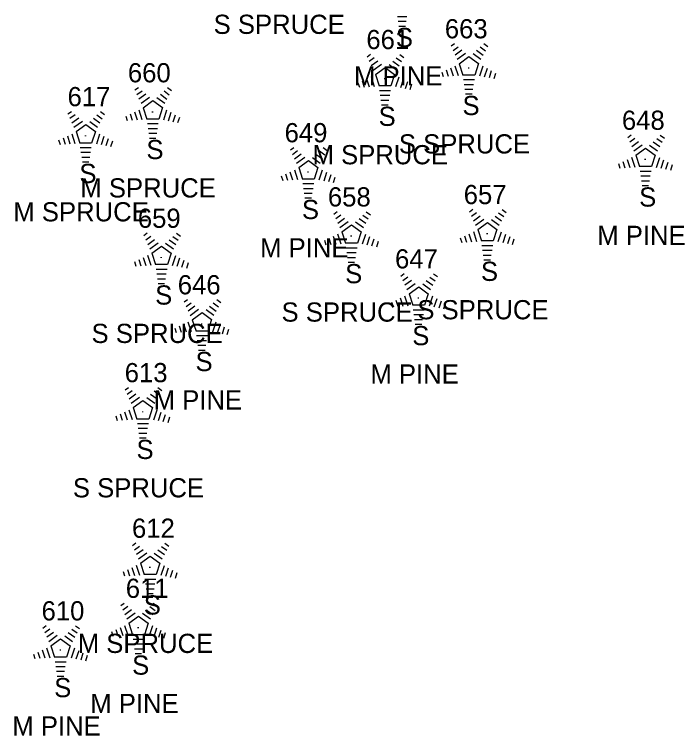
# Model space of a CAD drawing. Extents: x 1545627 to 1546562, y 571176 to 576667.
# Drawn here: x 1546282.1 to 1546351.9, y 572031.2 to 572106.4 of the extents above; entities that cross this region are included whole.
import ezdxf

# ---------------------------------------------------------------- set-up
doc = ezdxf.new("R2010")
doc.units = 0
for name, color, linetype in [('L_A', 7, 'Continuous'), ('L_C', 7, 'Continuous'), ('L_I', 7, 'Continuous'), ('LTC', 7, 'Continuous')]:
    doc.layers.add(name, color=color, linetype=linetype)

msp = doc.modelspace()

# ---------------------------------------------------------------- linework, layer by layer
at = {"layer": 'LTC'}
for p, q in [((1546323.001, 572106.113), (1546322.013, 572106.113)), ((1546322.917, 572105.613), (1546322.086, 572105.613)), ((1546322.834, 572105.113), (1546322.159, 572105.113)), ((1546327.598, 572103.074), (1546327.953, 572103.331)), ((1546327.808, 572102.608), (1546328.337, 572102.992)), ((1546330.996, 572103.314), (1546331.416, 572103.009)), ((1546328.017, 572102.142), (1546328.721, 572102.654)), ((1546328.227, 572101.677), (1546329.105, 572102.314)), ((1546329.883, 572102.269), (1546330.693, 572101.68)), ((1546330.254, 572102.617), (1546330.934, 572102.124)), ((1546330.625, 572102.966), (1546331.175, 572102.567)), ((1546318.855, 572101.947), (1546319.209, 572102.204)), ((1546319.064, 572101.481), (1546319.594, 572101.865)), ((1546319.274, 572101.015), (1546319.978, 572101.527)), ((1546321.511, 572101.49), (1546322.19, 572100.997)), ((1546321.882, 572101.839), (1546322.431, 572101.439)), ((1546322.253, 572102.187), (1546322.672, 572101.882)), ((1546328.451, 572101.222), (1546329.463, 572101.956)), ((1546329.463, 572101.956), (1546330.46, 572101.231)), ((1546319.484, 572100.549), (1546320.362, 572101.187)), ((1546319.708, 572100.094), (1546320.72, 572100.829)), ((1546320.72, 572100.829), (1546321.717, 572100.104)), ((1546321.14, 572101.142), (1546321.949, 572100.553)), ((1546327.541, 572100.786), (1546327.813, 572099.951)), ((1546327.997, 572101.002), (1546328.328, 572099.983)), ((1546328.451, 572101.222), (1546328.839, 572100.028)), ((1546330.46, 572101.231), (1546330.069, 572100.028)), ((1546330.898, 572100.96), (1546330.56, 572099.921)), ((1546319.708, 572100.094), (1546320.095, 572098.901)), ((1546321.717, 572100.104), (1546321.326, 572098.901)), ((1546326.631, 572100.353), (1546326.783, 572099.885)), ((1546327.086, 572100.569), (1546327.298, 572099.918)), ((1546330.069, 572100.028), (1546328.839, 572100.028)), ((1546331.342, 572100.71), (1546331.055, 572099.825)), ((1546331.787, 572100.46), (1546331.55, 572099.73)), ((1546332.231, 572100.209), (1546332.044, 572099.635)), ((1546317.887, 572099.226), (1546318.039, 572098.758)), ((1546318.343, 572099.442), (1546318.554, 572098.791)), ((1546318.798, 572099.659), (1546319.069, 572098.824)), ((1546319.254, 572099.875), (1546319.584, 572098.856)), ((1546322.154, 572099.833), (1546321.816, 572098.794)), ((1546322.599, 572099.583), (1546322.311, 572098.698)), ((1546323.044, 572099.333), (1546322.806, 572098.603)), ((1546330.031, 572099.528), (1546328.886, 572099.528)), ((1546294.657, 572098.487), (1546295.012, 572098.744)), ((1546298.055, 572098.727), (1546298.474, 572098.423)), ((1546321.326, 572098.901), (1546320.095, 572098.901)), ((1546323.488, 572099.082), (1546323.301, 572098.508)), ((1546329.947, 572099.028), (1546328.959, 572099.028)), ((1546329.863, 572098.528), (1546329.031, 572098.528)), ((1546294.867, 572098.021), (1546295.396, 572098.406)), ((1546295.076, 572097.556), (1546295.78, 572098.067)), ((1546295.286, 572097.09), (1546296.164, 572097.728)), ((1546297.313, 572098.031), (1546297.992, 572097.537)), ((1546297.684, 572098.379), (1546298.234, 572097.98)), ((1546321.287, 572098.401), (1546320.143, 572098.401)), ((1546321.204, 572097.901), (1546320.215, 572097.901)), ((1546329.779, 572098.028), (1546329.104, 572098.028)), ((1546295.51, 572096.635), (1546296.522, 572097.369)), ((1546296.522, 572097.369), (1546297.519, 572096.644)), ((1546296.942, 572097.682), (1546297.752, 572097.094)), ((1546321.12, 572097.401), (1546320.288, 572097.401)), ((1546287.671, 572095.998), (1546288.026, 572096.255)), ((1546291.07, 572096.238), (1546291.489, 572095.933)), ((1546295.056, 572096.416), (1546295.387, 572095.396)), ((1546295.51, 572096.635), (1546295.897, 572095.441)), ((1546297.519, 572096.644), (1546297.128, 572095.441)), ((1546297.957, 572096.374), (1546297.619, 572095.334)), ((1546321.036, 572096.901), (1546320.361, 572096.901)), ((1546287.881, 572095.532), (1546288.41, 572095.916)), ((1546288.091, 572095.066), (1546288.794, 572095.578)), ((1546290.328, 572095.541), (1546291.007, 572095.048)), ((1546290.699, 572095.89), (1546291.248, 572095.491)), ((1546293.689, 572095.766), (1546293.842, 572095.298)), ((1546294.145, 572095.983), (1546294.357, 572095.331)), ((1546294.6, 572096.199), (1546294.872, 572095.364)), ((1546298.401, 572096.123), (1546298.114, 572095.239)), ((1546298.846, 572095.873), (1546298.609, 572095.144)), ((1546299.29, 572095.623), (1546299.103, 572095.049)), ((1546288.3, 572094.601), (1546289.179, 572095.238)), ((1546288.525, 572094.146), (1546289.536, 572094.88)), ((1546289.536, 572094.88), (1546290.534, 572094.155)), ((1546289.956, 572095.193), (1546290.766, 572094.604)), ((1546297.128, 572095.441), (1546295.897, 572095.441)), ((1546297.089, 572094.941), (1546295.945, 572094.941)), ((1546288.525, 572094.146), (1546288.912, 572092.952)), ((1546290.534, 572094.155), (1546290.142, 572092.952)), ((1546297.006, 572094.441), (1546296.017, 572094.441)), ((1546286.704, 572093.277), (1546286.856, 572092.809)), ((1546287.159, 572093.493), (1546287.371, 572092.842)), ((1546287.615, 572093.71), (1546287.886, 572092.875)), ((1546288.07, 572093.926), (1546288.401, 572092.907)), ((1546290.971, 572093.884), (1546290.633, 572092.845)), ((1546291.416, 572093.634), (1546291.128, 572092.749)), ((1546291.86, 572093.384), (1546291.623, 572092.654)), ((1546296.922, 572093.941), (1546296.09, 572093.941)), ((1546296.838, 572093.441), (1546296.163, 572093.441)), ((1546346.004, 572093.538), (1546346.358, 572093.795)), ((1546346.213, 572093.072), (1546346.743, 572093.457)), ((1546349.031, 572093.43), (1546349.581, 572093.031)), ((1546349.402, 572093.778), (1546349.821, 572093.474)), ((1546290.142, 572092.952), (1546288.912, 572092.952)), ((1546290.104, 572092.452), (1546288.959, 572092.452)), ((1546292.304, 572093.133), (1546292.118, 572092.559)), ((1546310.865, 572092.241), (1546311.219, 572092.498)), ((1546314.263, 572092.481), (1546314.682, 572092.176)), ((1546346.423, 572092.607), (1546347.127, 572093.118)), ((1546346.633, 572092.141), (1546347.511, 572092.779)), ((1546348.289, 572092.733), (1546349.098, 572092.145)), ((1546348.66, 572093.082), (1546349.339, 572092.588)), ((1546290.02, 572091.952), (1546289.032, 572091.952)), ((1546311.074, 572091.775), (1546311.604, 572092.159)), ((1546311.284, 572091.309), (1546311.988, 572091.821)), ((1546313.521, 572091.784), (1546314.2, 572091.291)), ((1546313.892, 572092.133), (1546314.442, 572091.734)), ((1546346.857, 572091.686), (1546347.869, 572092.42)), ((1546347.869, 572092.42), (1546348.866, 572091.695)), ((1546348.866, 572091.695), (1546348.475, 572090.492)), ((1546289.936, 572091.452), (1546289.105, 572091.452)), ((1546289.853, 572090.952), (1546289.178, 572090.952)), ((1546311.494, 572090.844), (1546312.372, 572091.481)), ((1546311.718, 572090.389), (1546312.73, 572091.123)), ((1546312.73, 572091.123), (1546313.727, 572090.398)), ((1546313.15, 572091.436), (1546313.959, 572090.847)), ((1546345.492, 572091.034), (1546345.703, 572090.382)), ((1546345.947, 572091.25), (1546346.218, 572090.415)), ((1546346.403, 572091.467), (1546346.733, 572090.447)), ((1546346.857, 572091.686), (1546347.244, 572090.492)), ((1546349.303, 572091.425), (1546348.966, 572090.385)), ((1546349.748, 572091.174), (1546349.461, 572090.29)), ((1546311.718, 572090.389), (1546312.105, 572089.195)), ((1546313.727, 572090.398), (1546313.336, 572089.195)), ((1546345.036, 572090.817), (1546345.188, 572090.349)), ((1546348.475, 572090.492), (1546347.244, 572090.492)), ((1546350.193, 572090.924), (1546349.956, 572090.195)), ((1546350.637, 572090.674), (1546350.45, 572090.1)), ((1546309.897, 572089.52), (1546310.049, 572089.052)), ((1546310.353, 572089.736), (1546310.564, 572089.085)), ((1546310.808, 572089.953), (1546311.079, 572089.118)), ((1546311.264, 572090.169), (1546311.594, 572089.15)), ((1546314.164, 572090.127), (1546313.827, 572089.088)), ((1546314.609, 572089.877), (1546314.322, 572088.992)), ((1546315.054, 572089.627), (1546314.817, 572088.897)), ((1546348.436, 572089.992), (1546347.292, 572089.992)), ((1546348.353, 572089.492), (1546347.364, 572089.492)), ((1546313.336, 572089.195), (1546312.105, 572089.195)), ((1546313.297, 572088.695), (1546312.153, 572088.695)), ((1546315.498, 572089.376), (1546315.311, 572088.802)), ((1546348.269, 572088.992), (1546347.437, 572088.992)), ((1546313.214, 572088.195), (1546312.225, 572088.195)), ((1546348.185, 572088.492), (1546347.51, 572088.492)), ((1546313.13, 572087.695), (1546312.298, 572087.695)), ((1546313.046, 572087.195), (1546312.371, 572087.195)), ((1546315.368, 572085.551), (1546315.723, 572085.808)), ((1546318.766, 572085.791), (1546319.186, 572085.487)), ((1546329.521, 572085.795), (1546329.876, 572086.052)), ((1546329.731, 572085.329), (1546330.26, 572085.713)), ((1546332.548, 572085.687), (1546333.098, 572085.288)), ((1546332.919, 572086.035), (1546333.339, 572085.73)), ((1546315.578, 572085.085), (1546316.107, 572085.469)), ((1546315.787, 572084.619), (1546316.491, 572085.131)), ((1546318.024, 572085.094), (1546318.703, 572084.601)), ((1546318.395, 572085.443), (1546318.945, 572085.044)), ((1546329.94, 572084.863), (1546330.644, 572085.375)), ((1546330.15, 572084.398), (1546331.028, 572085.035)), ((1546331.806, 572084.99), (1546332.616, 572084.401)), ((1546332.177, 572085.338), (1546332.856, 572084.845)), ((1546315.997, 572084.154), (1546316.875, 572084.792)), ((1546316.221, 572083.699), (1546317.233, 572084.433)), ((1546317.233, 572084.433), (1546318.23, 572083.708)), ((1546317.653, 572084.746), (1546318.463, 572084.157)), ((1546330.374, 572083.943), (1546331.386, 572084.677)), ((1546331.386, 572084.677), (1546332.383, 572083.952)), ((1546295.569, 572083.326), (1546295.923, 572083.583)), ((1546298.967, 572083.566), (1546299.386, 572083.262)), ((1546315.767, 572083.479), (1546316.098, 572082.46)), ((1546316.221, 572083.699), (1546316.608, 572082.505)), ((1546318.23, 572083.708), (1546317.839, 572082.505)), ((1546318.668, 572083.437), (1546318.33, 572082.398)), ((1546329.464, 572083.507), (1546329.736, 572082.672)), ((1546329.92, 572083.723), (1546330.251, 572082.704)), ((1546330.374, 572083.943), (1546330.761, 572082.749)), ((1546332.383, 572083.952), (1546331.992, 572082.749)), ((1546332.821, 572083.681), (1546332.483, 572082.642)), ((1546333.265, 572083.431), (1546332.978, 572082.546)), ((1546295.778, 572082.86), (1546296.307, 572083.245)), ((1546295.988, 572082.395), (1546296.692, 572082.906)), ((1546298.225, 572082.87), (1546298.904, 572082.376)), ((1546298.596, 572083.218), (1546299.145, 572082.819)), ((1546314.401, 572082.83), (1546314.553, 572082.362)), ((1546314.856, 572083.047), (1546315.068, 572082.395)), ((1546315.311, 572083.263), (1546315.583, 572082.428)), ((1546319.112, 572083.187), (1546318.825, 572082.302)), ((1546319.557, 572082.937), (1546319.32, 572082.207)), ((1546320.001, 572082.687), (1546319.814, 572082.112)), ((1546328.554, 572083.074), (1546328.706, 572082.606)), ((1546329.009, 572083.29), (1546329.221, 572082.639)), ((1546331.992, 572082.749), (1546330.761, 572082.749)), ((1546333.71, 572083.181), (1546333.473, 572082.451)), ((1546334.154, 572082.93), (1546333.967, 572082.356)), ((1546296.197, 572081.929), (1546297.076, 572082.567)), ((1546296.422, 572081.474), (1546297.434, 572082.208)), ((1546297.434, 572082.208), (1546298.431, 572081.483)), ((1546297.854, 572082.521), (1546298.663, 572081.932)), ((1546317.839, 572082.505), (1546316.608, 572082.505)), ((1546317.801, 572082.005), (1546316.656, 572082.005)), ((1546331.954, 572082.249), (1546330.809, 572082.249)), ((1546295.967, 572081.255), (1546296.298, 572080.235)), ((1546296.422, 572081.474), (1546296.809, 572080.28)), ((1546298.431, 572081.483), (1546298.039, 572080.28)), ((1546298.868, 572081.212), (1546298.53, 572080.173)), ((1546317.717, 572081.505), (1546316.728, 572081.505)), ((1546331.87, 572081.749), (1546330.881, 572081.749)), ((1546331.786, 572081.249), (1546330.954, 572081.249)), ((1546294.601, 572080.605), (1546294.753, 572080.137)), ((1546295.057, 572080.822), (1546295.268, 572080.17)), ((1546295.512, 572081.038), (1546295.783, 572080.203)), ((1546299.313, 572080.962), (1546299.025, 572080.077)), ((1546299.757, 572080.712), (1546299.52, 572079.982)), ((1546300.202, 572080.462), (1546300.015, 572079.887)), ((1546317.633, 572081.005), (1546316.801, 572081.005)), ((1546317.549, 572080.505), (1546316.874, 572080.505)), ((1546331.702, 572080.749), (1546331.027, 572080.749)), ((1546298.039, 572080.28), (1546296.809, 572080.28)), ((1546298.001, 572079.78), (1546296.857, 572079.78)), ((1546297.917, 572079.28), (1546296.929, 572079.28)), ((1546322.361, 572079.094), (1546322.716, 572079.351)), ((1546322.571, 572078.628), (1546323.1, 572079.012)), ((1546325.388, 572078.986), (1546325.938, 572078.587)), ((1546325.76, 572079.334), (1546326.179, 572079.029)), ((1546297.834, 572078.78), (1546297.002, 572078.78)), ((1546297.75, 572078.28), (1546297.075, 572078.28)), ((1546322.781, 572078.162), (1546323.484, 572078.674)), ((1546322.99, 572077.697), (1546323.868, 572078.334)), ((1546324.646, 572078.289), (1546325.456, 572077.7)), ((1546325.018, 572078.637), (1546325.697, 572078.144)), ((1546323.215, 572077.242), (1546324.226, 572077.976)), ((1546324.226, 572077.976), (1546325.223, 572077.251)), ((1546322.305, 572076.806), (1546322.576, 572075.971)), ((1546322.76, 572077.022), (1546323.091, 572076.003)), ((1546323.215, 572077.242), (1546323.602, 572076.048)), ((1546325.223, 572077.251), (1546324.832, 572076.048)), ((1546325.661, 572076.98), (1546325.323, 572075.941)), ((1546326.106, 572076.73), (1546325.818, 572075.845)), ((1546299.777, 572076.395), (1546300.131, 572076.653)), ((1546299.986, 572075.93), (1546300.515, 572076.314)), ((1546300.196, 572075.464), (1546300.899, 572075.975)), ((1546302.433, 572075.939), (1546303.112, 572075.445)), ((1546302.804, 572076.287), (1546303.353, 572075.888)), ((1546303.175, 572076.636), (1546303.594, 572076.331)), ((1546321.394, 572076.373), (1546321.546, 572075.905)), ((1546321.849, 572076.589), (1546322.061, 572075.938)), ((1546324.832, 572076.048), (1546323.602, 572076.048)), ((1546326.55, 572076.48), (1546326.313, 572075.75)), ((1546326.994, 572076.229), (1546326.808, 572075.655)), ((1546300.405, 572074.998), (1546301.284, 572075.636)), ((1546300.63, 572074.543), (1546301.642, 572075.278)), ((1546301.642, 572075.278), (1546302.639, 572074.553)), ((1546302.062, 572075.591), (1546302.871, 572075.002)), ((1546324.794, 572075.548), (1546323.649, 572075.548)), ((1546300.63, 572074.543), (1546301.017, 572073.35)), ((1546302.639, 572074.553), (1546302.247, 572073.35)), ((1546324.71, 572075.048), (1546323.722, 572075.048)), ((1546324.626, 572074.548), (1546323.795, 572074.548)), ((1546298.809, 572073.674), (1546298.961, 572073.206)), ((1546299.264, 572073.891), (1546299.476, 572073.239)), ((1546299.72, 572074.108), (1546299.991, 572073.272)), ((1546300.175, 572074.324), (1546300.506, 572073.305)), ((1546303.076, 572074.282), (1546302.738, 572073.242)), ((1546303.521, 572074.031), (1546303.233, 572073.147)), ((1546303.965, 572073.781), (1546303.728, 572073.052)), ((1546324.543, 572074.048), (1546323.868, 572074.048)), ((1546302.247, 572073.35), (1546301.017, 572073.35)), ((1546304.409, 572073.531), (1546304.223, 572072.957)), ((1546302.209, 572072.85), (1546301.064, 572072.85)), ((1546302.125, 572072.35), (1546301.137, 572072.35)), ((1546302.042, 572071.85), (1546301.21, 572071.85)), ((1546301.958, 572071.35), (1546301.283, 572071.35)), ((1546293.625, 572067.238), (1546293.98, 572067.496)), ((1546293.835, 572066.773), (1546294.364, 572067.157)), ((1546296.652, 572067.131), (1546297.202, 572066.731)), ((1546297.023, 572067.479), (1546297.442, 572067.174)), ((1546294.044, 572066.307), (1546294.748, 572066.818)), ((1546294.254, 572065.841), (1546295.132, 572066.479)), ((1546295.91, 572066.434), (1546296.719, 572065.845)), ((1546296.281, 572066.782), (1546296.96, 572066.288)), ((1546294.478, 572065.386), (1546295.49, 572066.121)), ((1546295.49, 572066.121), (1546296.487, 572065.396)), ((1546296.487, 572065.396), (1546296.096, 572064.193)), ((1546293.113, 572064.734), (1546293.325, 572064.083)), ((1546293.568, 572064.951), (1546293.84, 572064.116)), ((1546294.024, 572065.167), (1546294.355, 572064.148)), ((1546294.478, 572065.386), (1546294.865, 572064.193)), ((1546296.924, 572065.125), (1546296.587, 572064.086)), ((1546297.369, 572064.875), (1546297.082, 572063.99)), ((1546292.657, 572064.518), (1546292.81, 572064.05)), ((1546296.096, 572064.193), (1546294.865, 572064.193)), ((1546297.814, 572064.625), (1546297.577, 572063.895)), ((1546298.258, 572064.374), (1546298.071, 572063.8)), ((1546296.057, 572063.693), (1546294.913, 572063.693)), ((1546295.974, 572063.193), (1546294.985, 572063.193)), ((1546295.89, 572062.693), (1546295.058, 572062.693)), ((1546295.806, 572062.193), (1546295.131, 572062.193)), ((1546294.383, 572051.028), (1546294.738, 572051.285)), ((1546297.782, 572051.268), (1546298.201, 572050.964)), ((1546294.593, 572050.563), (1546295.122, 572050.947)), ((1546294.803, 572050.097), (1546295.506, 572050.608)), ((1546297.04, 572050.572), (1546297.719, 572050.078)), ((1546297.41, 572050.92), (1546297.96, 572050.521)), ((1546295.012, 572049.631), (1546295.89, 572050.269)), ((1546295.237, 572049.176), (1546296.248, 572049.91)), ((1546296.248, 572049.91), (1546297.245, 572049.185)), ((1546296.668, 572050.223), (1546297.478, 572049.635)), ((1546294.782, 572048.957), (1546295.113, 572047.938)), ((1546295.237, 572049.176), (1546295.624, 572047.983)), ((1546297.245, 572049.185), (1546296.854, 572047.983)), ((1546297.683, 572048.915), (1546297.345, 572047.875)), ((1546293.416, 572048.307), (1546293.568, 572047.839)), ((1546293.871, 572048.524), (1546294.083, 572047.872)), ((1546294.327, 572048.74), (1546294.598, 572047.905)), ((1546298.127, 572048.664), (1546297.84, 572047.78)), ((1546298.572, 572048.414), (1546298.335, 572047.685)), ((1546299.016, 572048.164), (1546298.83, 572047.59)), ((1546296.854, 572047.983), (1546295.624, 572047.983)), ((1546296.816, 572047.483), (1546295.671, 572047.483)), ((1546296.732, 572046.983), (1546295.744, 572046.983)), ((1546296.648, 572046.483), (1546295.817, 572046.483)), ((1546296.565, 572045.983), (1546295.89, 572045.983)), ((1546293.17, 572044.765), (1546293.525, 572045.023)), ((1546293.38, 572044.3), (1546293.909, 572044.684)), ((1546296.198, 572044.657), (1546296.747, 572044.258)), ((1546296.569, 572045.006), (1546296.988, 572044.701)), ((1546293.59, 572043.834), (1546294.293, 572044.345)), ((1546293.799, 572043.368), (1546294.678, 572044.006)), ((1546294.024, 572042.913), (1546295.035, 572043.648)), ((1546295.035, 572043.648), (1546296.033, 572042.923)), ((1546295.455, 572043.961), (1546296.265, 572043.372)), ((1546295.827, 572044.309), (1546296.506, 572043.815)), ((1546294.024, 572042.913), (1546294.411, 572041.72)), ((1546296.033, 572042.923), (1546295.641, 572041.72)), ((1546285.047, 572042.419), (1546285.401, 572042.677)), ((1546285.256, 572041.954), (1546285.785, 572042.338)), ((1546288.074, 572042.311), (1546288.623, 572041.912)), ((1546288.445, 572042.66), (1546288.864, 572042.355)), ((1546292.658, 572042.261), (1546292.87, 572041.609)), ((1546293.114, 572042.478), (1546293.385, 572041.642)), ((1546293.569, 572042.694), (1546293.9, 572041.675)), ((1546296.47, 572042.652), (1546296.132, 572041.612)), ((1546296.915, 572042.401), (1546296.627, 572041.517)), ((1546297.359, 572042.151), (1546297.122, 572041.422)), ((1546285.466, 572041.488), (1546286.169, 572041.999)), ((1546285.675, 572041.022), (1546286.554, 572041.66)), ((1546287.332, 572041.615), (1546288.141, 572041.026)), ((1546287.703, 572041.963), (1546288.382, 572041.469)), ((1546292.203, 572042.044), (1546292.355, 572041.576)), ((1546295.641, 572041.72), (1546294.411, 572041.72)), ((1546297.803, 572041.901), (1546297.617, 572041.327)), ((1546285.9, 572040.567), (1546286.912, 572041.302)), ((1546286.912, 572041.302), (1546287.909, 572040.577)), ((1546295.603, 572041.22), (1546294.458, 572041.22)), ((1546295.519, 572040.72), (1546294.531, 572040.72)), ((1546284.534, 572039.915), (1546284.746, 572039.264)), ((1546284.99, 572040.132), (1546285.261, 572039.296)), ((1546285.445, 572040.348), (1546285.776, 572039.329)), ((1546285.9, 572040.567), (1546286.287, 572039.374)), ((1546287.909, 572040.577), (1546287.517, 572039.374)), ((1546288.346, 572040.306), (1546288.008, 572039.266)), ((1546288.791, 572040.056), (1546288.503, 572039.171)), ((1546295.435, 572040.22), (1546294.604, 572040.22)), ((1546284.079, 572039.699), (1546284.231, 572039.231)), ((1546287.517, 572039.374), (1546286.287, 572039.374)), ((1546289.235, 572039.806), (1546288.998, 572039.076)), ((1546289.679, 572039.555), (1546289.493, 572038.981)), ((1546295.352, 572039.72), (1546294.677, 572039.72)), ((1546287.479, 572038.874), (1546286.334, 572038.874)), ((1546287.395, 572038.374), (1546286.407, 572038.374)), ((1546287.312, 572037.874), (1546286.48, 572037.874)), ((1546287.228, 572037.374), (1546286.553, 572037.374))]:
    msp.add_line(p, q, dxfattribs=at)

# ---------------------------------------------------------------- texts
at = {"layer": 'L_A'}
for p in [(1546321.843, 572102.95), (1546328.789, 572095.865), (1546320.045, 572094.738), (1546295.848, 572091.279), (1546288.862, 572088.789), (1546347.195, 572086.33), (1546312.056, 572085.032), (1546330.712, 572078.586), (1546316.559, 572078.343), (1546296.759, 572076.118), (1546323.552, 572071.885), (1546300.967, 572069.187), (1546294.816, 572060.03), (1546295.574, 572043.82), (1546294.361, 572037.557), (1546286.237, 572035.211)]:
    msp.add_text('S', height=2, dxfattribs=at).set_placement(p)
at = {"layer": 'L_C'}
for s, p in [('S SPRUCE', (1546302.852, 572104.324)), ('M PINE', (1546317.481, 572098.95)), ('S SPRUCE', (1546322.159, 572091.865)), ('M SPRUCE', (1546313.164, 572090.738)), ('M SPRUCE', (1546288.966, 572087.279)), ('M SPRUCE', (1546281.98, 572084.789)), ('M PINE', (1546342.832, 572082.33)), ('M PINE', (1546307.693, 572081.032)), ('S SPRUCE', (1546309.929, 572074.343)), ('S SPRUCE', (1546324.082, 572074.586)), ('S SPRUCE', (1546290.129, 572072.118)), ('M PINE', (1546319.19, 572067.885)), ('M PINE', (1546296.605, 572065.187)), ('S SPRUCE', (1546288.186, 572056.03)), ('M SPRUCE', (1546288.692, 572039.82)), ('M PINE', (1546289.999, 572033.557)), ('M PINE', (1546281.875, 572031.211))]:
    msp.add_text(s, height=2, dxfattribs=at).set_placement(p)
at = {"layer": 'L_I'}
for s, p in [('663', (1546326.946, 572103.865)), ('661', (1546318.77, 572102.738)), ('660', (1546293.919, 572099.279)), ('617', (1546287.634, 572096.789)), ('648', (1546345.399, 572094.33)), ('649', (1546310.252, 572093.032)), ('658', (1546314.763, 572086.343)), ('657', (1546328.916, 572086.586)), ('659', (1546294.956, 572084.118)), ('647', (1546321.757, 572079.885)), ('646', (1546299.117, 572077.187)), ('613', (1546293.587, 572068.03)), ('612', (1546294.346, 572051.82)), ('611', (1546293.7, 572045.557)), ('610', (1546284.922, 572043.211))]:
    msp.add_text(s, height=2, dxfattribs=at).set_placement(p)
at = {"layer": 'LTC'}
for p in [(1546329.346, 572100.969), (1546320.602, 572099.842), (1546296.404, 572096.383), (1546289.419, 572093.893), (1546347.751, 572091.434), (1546312.612, 572090.136), (1546331.269, 572083.69), (1546317.116, 572083.447), (1546297.316, 572081.222), (1546324.109, 572076.989), (1546301.524, 572074.291), (1546295.372, 572065.134), (1546296.131, 572048.924), (1546294.918, 572042.661), (1546286.794, 572040.315)]:
    msp.add_text('.', height=1.037, rotation=270, dxfattribs=at).set_placement(p)

doc.saveas('drawing.dxf')
